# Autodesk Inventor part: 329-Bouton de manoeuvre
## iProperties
Author: Philippe
Shininess: 69.0
Angle Display Precision: 2
Document Length Units: 11269
Document Angle Units: 11283
Document Time Units: 11279
Document Mass Units: 11290
Document Length Units Precision: 3
Document Angle Units Precision: 2
Compacted: False
PropertySet Name: _Private Model Information
Created: 2001-12
Part Number: 329-Bouton de manoeuvre
Material: Par défaut
Document SubType Name: Modélisation
Designer: Philippe
Control State: 0
Master: False
Checked Out: False
PropertySet Name: Design Tracking Control
Density: 0.0
Volumn: 0.0
Area: 0.0
PropertySet Name: Model Information
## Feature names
1. Révolution1 [Revolution]
2. Révolution2 [Revolution]
3. Réseau circulaire1 [Circular Pattern]
4. Extrusion1
5. Congé1 [Fillet]
6. Extrusion2
7. Extrusion3
